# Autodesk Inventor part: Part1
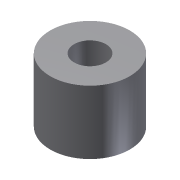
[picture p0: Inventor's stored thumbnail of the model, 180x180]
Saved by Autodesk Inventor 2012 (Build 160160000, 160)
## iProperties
Shininess: 77.0
Angle Display Precision: 2
Document Length Units: 11269
Document Angle Units: 11279
Document Time Units: 11290
Document Mass Units: 11283
Document Length Units Precision: 3
Document Angle Units Precision: 2
Created: 2002-01
Part Number: Part1
Document SubType Name: Modeling
Designer: ***
Density: 1 g/cm^3
Material: Default
Density: 0.0
Volumn: 0.0
Area: 0.0
PropertySet Name: Model Information
Control State: 0
Master: False
Checked Out: False
Author: ***
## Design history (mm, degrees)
sketch "Sketch1"
  geometry: C1 r 25 at (0, 0); C2 r 10 at (0, 0)
  constraints: 2 centre point, 1 coincident
  dimensions: "d0" = 50 diameter of C1; "d1" = 20 diameter of C2
extrude "Extrusion1" new body sketch "Sketch1" distance "d2" = 40; taper "d3" = 0 deg
body "Solid1"
